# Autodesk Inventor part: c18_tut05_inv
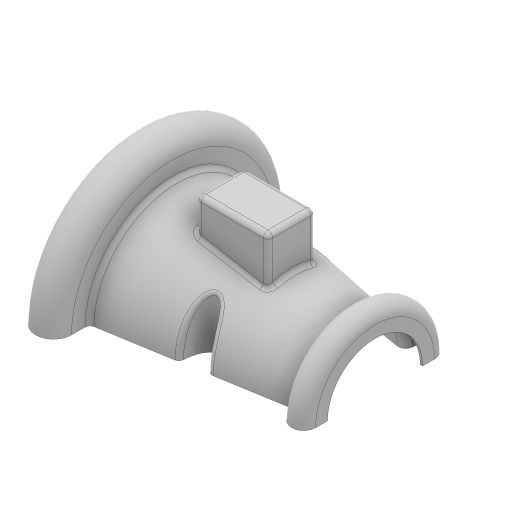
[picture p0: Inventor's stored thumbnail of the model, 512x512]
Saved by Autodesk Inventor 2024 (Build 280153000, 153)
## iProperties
Created: 2017-06
Part Number: c18_tut05_inv
Material: Generic
Document SubType Name: Modeling
Designer: CADCIM 00
Density: 1 g/cm^3
Appearance: Default
Author: CADCIM 00
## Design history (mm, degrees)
feature "RevolutionSrf1" dims angle "d9" = 180 deg
extrude_surface "ExtrusionSrf1" dims "d12" = 30, "d13" = 0
mirror "Mirror1"
feature "Trim3"
feature "Trim4"
feature "Trim5"
feature "Trim6"
workplane "Work Plane1"
split "Split1"
delete_face "Delete Face1"
sketch "3D Sketch1"
feature "Stitch Surface1"
fillet "Fillet1" dims "d25" = 2
thicken "Thicken1" dims "d26" = 1
body "Solid1"
sketch "Sketch3"
  geometry: L1 (35, 10)-(65, 10); L2 (65, 10)-(65, -10); L3 (65, -10)-(35, -10); L4 (35, -10)-(35, 10); 1 further point
  constraints: 8 end point, 2 parallel, 1 horizontal, 1 perpendicular
  dimensions: "d15" = 30 distance of L1.start L1.end; "d16" = 20 distance of L1.end L2.end; "d17" = 10 distance from line of point (0, 0) L3; "d18" = 35 distance from line of L4 point (0, 0)
sketch "Sketch1"
  geometry: L1 (0, 30)-(0, 42.5); L2 (15, 42.5)-(15, 35); L3 (15, 35)-(90, 22.5); L4 (100, 25)-(100, 20); L5 (90, 25)-(90, 22.5); L6 (0, 0)-(90, 0); A1 r 7.5 centre (7.5, 42.5) between (15, 42.5) and (0, 42.5); A2 r 5 centre (95, 25) between (100, 25) and (90, 25)
  constraints: 12 end point, 4 point on circle, 4 tangent, 2 centre point, 2 parallel, 2 vertical, 2 vertical alignment, 1 horizontal
  dimensions: "d0" = 60 diameter of L1.start L6; "d1" = 70 diameter of L2.end L6; "d2" = 85 diameter of L1.end L6; "d3" = 100 distance between parallel lines of L4 L1; "d4" = 7.5 radius of A1; "d5" = 5 radius of A2; "d6" = 40 diameter of L4.end L6; "d7" = 45 diameter of L3.end L6; "d8" = 50 diameter of L4.start L6
body "Srf1"
sketch "Sketch2" dims "d10" = 5, "d11" = 10
  geometry: L1 (90, 22.5)-(15, 35) reference; 2 further points; 1 other entity
  constraints: 1 midpoint, 2 other
body "Srf2"
body "Srf3"
node "Edges1"
body "Srf4"
body "Srf5"
body "Srf6"
extrude_surface "ExtrusionSrf2"
feature "LoftSrf1" dims "d19" = 0, "d20" = 90 deg, "d21" = 0, "d22" = 90 deg
patch "Boundary Patch1" dims "d23" = 5, "d24" = 0
other parameters: "d14" = 45
